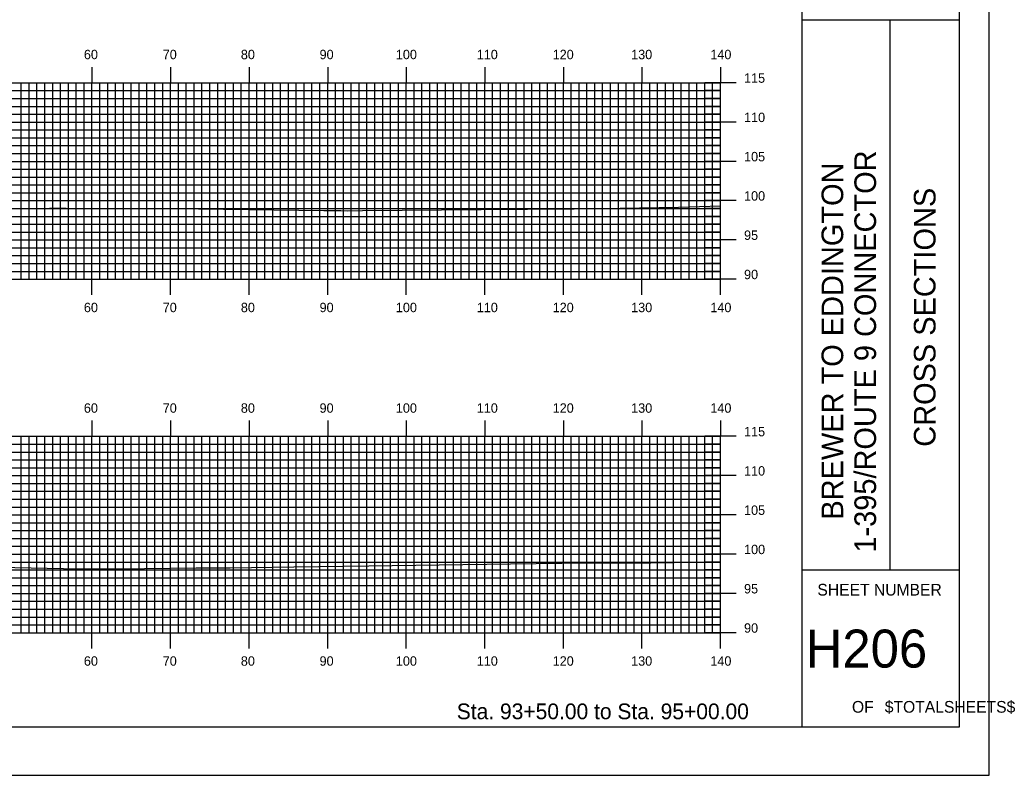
# Model space of a CAD drawing. Extents: x 1765333 to 1765676, y 442591 to 442811.
# Drawn here: x 1765549.2 to 1765675.9, y 442590.5 to 442686.7 of the extents above; entities that cross this region are included whole.
import ezdxf

# ---------------------------------------------------------------- set-up
doc = ezdxf.new("R2010")
doc.units = 0
for name, color, linetype in [('BORDER', 7, 'Continuous'), ('H_V ANNOTATION', 7, 'Continuous'), ('MAJOR', 7, 'Continuous'), ('MINOR', 7, 'Continuous'), ('PLOT BOUNDARY', 7, 'Continuous'), ('S_Roadway_Centerline', 7, 'Continuous')]:
    doc.layers.add(name, color=color, linetype=linetype)

msp = doc.modelspace()

# ---------------------------------------------------------------- linework, layer by layer
at = {"layer": 'BORDER'}
for p, q in [((1765648.77, 442596.67), (1765648.77, 442806.67)), ((1765648.77, 442686.67), (1765668.77, 442686.67)), ((1765659.95, 442616.67), (1765659.95, 442686.67)), ((1765648.77, 442616.67), (1765668.77, 442616.67))]:
    msp.add_line(p, q, dxfattribs=at)
msp.add_lwpolyline([(1765348.77, 442596.67), (1765668.77, 442596.67), (1765668.77, 442806.67), (1765348.77, 442806.67)], close=True, dxfattribs=at)
at = {"layer": 'MAJOR'}
for p, q in [((1765558.37, 442680.67), (1765558.37, 442678.67)), ((1765568.37, 442680.67), (1765568.37, 442678.67)), ((1765578.37, 442680.67), (1765578.37, 442678.67)), ((1765588.37, 442680.67), (1765588.37, 442678.67)), ((1765598.37, 442680.67), (1765598.37, 442678.67)), ((1765608.37, 442680.67), (1765608.37, 442678.67)), ((1765618.37, 442680.67), (1765618.37, 442678.67)), ((1765628.37, 442680.67), (1765628.37, 442678.67)), ((1765638.37, 442680.67), (1765638.37, 442678.67)), ((1765358.37, 442678.67), (1765638.37, 442678.67)), ((1765358.37, 442678.67), (1765638.37, 442678.67)), ((1765558.37, 442653.67), (1765558.37, 442678.67)), ((1765568.37, 442653.67), (1765568.37, 442678.67)), ((1765578.37, 442653.67), (1765578.37, 442678.67)), ((1765588.37, 442653.67), (1765588.37, 442678.67)), ((1765598.37, 442653.67), (1765598.37, 442678.67)), ((1765608.37, 442653.67), (1765608.37, 442678.67)), ((1765618.37, 442653.67), (1765618.37, 442678.67)), ((1765628.37, 442653.67), (1765628.37, 442678.67)), ((1765640.37, 442678.67), (1765636.37, 442678.67)), ((1765638.37, 442653.67), (1765638.37, 442678.67)), ((1765638.37, 442653.67), (1765638.37, 442678.67)), ((1765358.37, 442673.67), (1765638.37, 442673.67)), ((1765640.37, 442673.67), (1765636.37, 442673.67)), ((1765358.37, 442668.67), (1765638.37, 442668.67)), ((1765640.37, 442668.67), (1765636.37, 442668.67)), ((1765358.37, 442663.67), (1765638.37, 442663.67)), ((1765640.37, 442663.67), (1765636.37, 442663.67)), ((1765358.37, 442658.67), (1765638.37, 442658.67)), ((1765640.37, 442658.67), (1765636.37, 442658.67)), ((1765358.37, 442653.67), (1765638.37, 442653.67)), ((1765358.37, 442653.67), (1765638.37, 442653.67)), ((1765558.37, 442651.66), (1765558.37, 442653.67)), ((1765568.37, 442651.66), (1765568.37, 442653.67)), ((1765578.37, 442651.66), (1765578.37, 442653.67)), ((1765588.37, 442651.66), (1765588.37, 442653.67)), ((1765598.37, 442651.66), (1765598.37, 442653.67)), ((1765608.37, 442651.66), (1765608.37, 442653.67)), ((1765618.37, 442651.66), (1765618.37, 442653.67)), ((1765628.37, 442651.66), (1765628.37, 442653.67)), ((1765640.37, 442653.67), (1765636.37, 442653.67)), ((1765638.37, 442651.66), (1765638.37, 442653.67)), ((1765558.37, 442635.67), (1765558.37, 442633.67)), ((1765568.37, 442635.67), (1765568.37, 442633.67)), ((1765578.37, 442635.67), (1765578.37, 442633.67)), ((1765588.37, 442635.67), (1765588.37, 442633.67)), ((1765598.37, 442635.67), (1765598.37, 442633.67)), ((1765608.37, 442635.67), (1765608.37, 442633.67)), ((1765618.37, 442635.67), (1765618.37, 442633.67)), ((1765628.37, 442635.67), (1765628.37, 442633.67)), ((1765638.37, 442635.67), (1765638.37, 442633.67)), ((1765358.37, 442633.67), (1765638.37, 442633.67)), ((1765358.37, 442633.67), (1765638.37, 442633.67)), ((1765558.37, 442608.67), (1765558.37, 442633.67)), ((1765568.37, 442608.67), (1765568.37, 442633.67)), ((1765578.37, 442608.67), (1765578.37, 442633.67)), ((1765588.37, 442608.67), (1765588.37, 442633.67)), ((1765598.37, 442608.67), (1765598.37, 442633.67)), ((1765608.37, 442608.67), (1765608.37, 442633.67)), ((1765618.37, 442608.67), (1765618.37, 442633.67)), ((1765628.37, 442608.67), (1765628.37, 442633.67)), ((1765640.37, 442633.67), (1765636.37, 442633.67)), ((1765638.37, 442608.67), (1765638.37, 442633.67)), ((1765638.37, 442608.67), (1765638.37, 442633.67)), ((1765358.37, 442628.67), (1765638.37, 442628.67)), ((1765640.37, 442628.67), (1765636.37, 442628.67)), ((1765358.37, 442623.67), (1765638.37, 442623.67)), ((1765640.37, 442623.67), (1765636.37, 442623.67)), ((1765358.37, 442618.67), (1765638.37, 442618.67)), ((1765640.37, 442618.67), (1765636.37, 442618.67)), ((1765358.37, 442613.67), (1765638.37, 442613.67)), ((1765640.37, 442613.67), (1765636.37, 442613.67)), ((1765358.37, 442608.67), (1765638.37, 442608.67)), ((1765358.37, 442608.67), (1765638.37, 442608.67)), ((1765558.37, 442606.66), (1765558.37, 442608.67)), ((1765568.37, 442606.66), (1765568.37, 442608.67)), ((1765578.37, 442606.66), (1765578.37, 442608.67)), ((1765588.37, 442606.66), (1765588.37, 442608.67)), ((1765598.37, 442606.66), (1765598.37, 442608.67)), ((1765608.37, 442606.66), (1765608.37, 442608.67)), ((1765618.37, 442606.66), (1765618.37, 442608.67)), ((1765628.37, 442606.66), (1765628.37, 442608.67)), ((1765640.37, 442608.67), (1765636.37, 442608.67)), ((1765638.37, 442606.66), (1765638.37, 442608.67))]:
    msp.add_line(p, q, dxfattribs=at)
at = {"layer": 'MINOR'}
for p, q in [((1765549.37, 442653.67), (1765549.37, 442678.67)), ((1765550.37, 442653.67), (1765550.37, 442678.67)), ((1765551.37, 442653.67), (1765551.37, 442678.67)), ((1765552.37, 442653.67), (1765552.37, 442678.67)), ((1765553.37, 442653.67), (1765553.37, 442678.67)), ((1765554.37, 442653.67), (1765554.37, 442678.67)), ((1765555.37, 442653.67), (1765555.37, 442678.67)), ((1765556.37, 442653.67), (1765556.37, 442678.67)), ((1765557.37, 442653.67), (1765557.37, 442678.67)), ((1765559.37, 442653.67), (1765559.37, 442678.67)), ((1765560.37, 442653.67), (1765560.37, 442678.67)), ((1765561.37, 442653.67), (1765561.37, 442678.67)), ((1765562.37, 442653.67), (1765562.37, 442678.67)), ((1765563.37, 442653.67), (1765563.37, 442678.67)), ((1765564.37, 442653.67), (1765564.37, 442678.67)), ((1765565.37, 442653.67), (1765565.37, 442678.67)), ((1765566.37, 442653.67), (1765566.37, 442678.67)), ((1765567.37, 442653.67), (1765567.37, 442678.67)), ((1765569.37, 442653.67), (1765569.37, 442678.67)), ((1765570.37, 442653.67), (1765570.37, 442678.67)), ((1765571.37, 442653.67), (1765571.37, 442678.67)), ((1765572.37, 442653.67), (1765572.37, 442678.67)), ((1765573.37, 442653.67), (1765573.37, 442678.67)), ((1765574.37, 442653.67), (1765574.37, 442678.67)), ((1765575.37, 442653.67), (1765575.37, 442678.67)), ((1765576.37, 442653.67), (1765576.37, 442678.67)), ((1765577.37, 442653.67), (1765577.37, 442678.67)), ((1765579.37, 442653.67), (1765579.37, 442678.67)), ((1765580.37, 442653.67), (1765580.37, 442678.67)), ((1765581.37, 442653.67), (1765581.37, 442678.67)), ((1765582.37, 442653.67), (1765582.37, 442678.67)), ((1765583.37, 442653.67), (1765583.37, 442678.67)), ((1765584.37, 442653.67), (1765584.37, 442678.67)), ((1765585.37, 442653.67), (1765585.37, 442678.67)), ((1765586.37, 442653.67), (1765586.37, 442678.67)), ((1765587.37, 442653.67), (1765587.37, 442678.67)), ((1765589.37, 442653.67), (1765589.37, 442678.67)), ((1765590.37, 442653.67), (1765590.37, 442678.67)), ((1765591.37, 442653.67), (1765591.37, 442678.67)), ((1765592.37, 442653.67), (1765592.37, 442678.67)), ((1765593.37, 442653.67), (1765593.37, 442678.67)), ((1765594.37, 442653.67), (1765594.37, 442678.67)), ((1765595.37, 442653.67), (1765595.37, 442678.67)), ((1765596.37, 442653.67), (1765596.37, 442678.67)), ((1765597.37, 442653.67), (1765597.37, 442678.67)), ((1765599.37, 442653.67), (1765599.37, 442678.67)), ((1765600.37, 442653.67), (1765600.37, 442678.67)), ((1765601.37, 442653.67), (1765601.37, 442678.67)), ((1765602.37, 442653.67), (1765602.37, 442678.67)), ((1765603.37, 442653.67), (1765603.37, 442678.67)), ((1765604.37, 442653.67), (1765604.37, 442678.67)), ((1765605.37, 442653.67), (1765605.37, 442678.67)), ((1765606.37, 442653.67), (1765606.37, 442678.67)), ((1765607.37, 442653.67), (1765607.37, 442678.67)), ((1765609.37, 442653.67), (1765609.37, 442678.67)), ((1765610.37, 442653.67), (1765610.37, 442678.67)), ((1765611.37, 442653.67), (1765611.37, 442678.67)), ((1765612.37, 442653.67), (1765612.37, 442678.67)), ((1765613.37, 442653.67), (1765613.37, 442678.67)), ((1765614.37, 442653.67), (1765614.37, 442678.67)), ((1765615.37, 442653.67), (1765615.37, 442678.67)), ((1765616.37, 442653.67), (1765616.37, 442678.67)), ((1765617.37, 442653.67), (1765617.37, 442678.67)), ((1765619.37, 442653.67), (1765619.37, 442678.67)), ((1765620.37, 442653.67), (1765620.37, 442678.67)), ((1765621.37, 442653.67), (1765621.37, 442678.67)), ((1765622.37, 442653.67), (1765622.37, 442678.67)), ((1765623.37, 442653.67), (1765623.37, 442678.67)), ((1765624.37, 442653.67), (1765624.37, 442678.67)), ((1765625.37, 442653.67), (1765625.37, 442678.67)), ((1765626.37, 442653.67), (1765626.37, 442678.67)), ((1765627.37, 442653.67), (1765627.37, 442678.67)), ((1765629.37, 442653.67), (1765629.37, 442678.67)), ((1765630.37, 442653.67), (1765630.37, 442678.67)), ((1765631.37, 442653.67), (1765631.37, 442678.67)), ((1765632.37, 442653.67), (1765632.37, 442678.67)), ((1765633.37, 442653.67), (1765633.37, 442678.67)), ((1765634.37, 442653.67), (1765634.37, 442678.67)), ((1765635.37, 442653.67), (1765635.37, 442678.67)), ((1765636.37, 442653.67), (1765636.37, 442678.67)), ((1765637.37, 442653.67), (1765637.37, 442678.67)), ((1765358.37, 442677.67), (1765638.37, 442677.67)), ((1765638.37, 442677.67), (1765636.37, 442677.67)), ((1765358.37, 442676.67), (1765638.37, 442676.67)), ((1765638.37, 442676.67), (1765636.37, 442676.67)), ((1765358.37, 442675.67), (1765638.37, 442675.67)), ((1765638.37, 442675.67), (1765636.37, 442675.67)), ((1765358.37, 442674.67), (1765638.37, 442674.67)), ((1765638.37, 442674.67), (1765636.37, 442674.67)), ((1765358.37, 442672.67), (1765638.37, 442672.67)), ((1765638.37, 442672.67), (1765636.37, 442672.67)), ((1765358.37, 442671.67), (1765638.37, 442671.67)), ((1765638.37, 442671.67), (1765636.37, 442671.67)), ((1765358.37, 442670.67), (1765638.37, 442670.67)), ((1765638.37, 442670.67), (1765636.37, 442670.67)), ((1765358.37, 442669.67), (1765638.37, 442669.67)), ((1765638.37, 442669.67), (1765636.37, 442669.67)), ((1765358.37, 442667.67), (1765638.37, 442667.67)), ((1765638.37, 442667.67), (1765636.37, 442667.67)), ((1765358.37, 442666.67), (1765638.37, 442666.67)), ((1765638.37, 442666.67), (1765636.37, 442666.67)), ((1765358.37, 442665.67), (1765638.37, 442665.67)), ((1765358.37, 442664.67), (1765638.37, 442664.67)), ((1765638.37, 442665.67), (1765636.37, 442665.67)), ((1765638.37, 442664.67), (1765636.37, 442664.67)), ((1765358.37, 442662.67), (1765638.37, 442662.67)), ((1765638.37, 442662.67), (1765636.37, 442662.67)), ((1765358.37, 442661.67), (1765638.37, 442661.67)), ((1765638.37, 442661.67), (1765636.37, 442661.67)), ((1765358.37, 442660.67), (1765638.37, 442660.67)), ((1765358.37, 442659.67), (1765638.37, 442659.67)), ((1765638.37, 442660.67), (1765636.37, 442660.67)), ((1765638.37, 442659.67), (1765636.37, 442659.67)), ((1765358.37, 442657.67), (1765638.37, 442657.67)), ((1765638.37, 442657.67), (1765636.37, 442657.67)), ((1765358.37, 442656.67), (1765638.37, 442656.67)), ((1765638.37, 442656.67), (1765636.37, 442656.67)), ((1765358.37, 442655.67), (1765638.37, 442655.67)), ((1765358.37, 442654.67), (1765638.37, 442654.67)), ((1765638.37, 442655.67), (1765636.37, 442655.67)), ((1765638.37, 442654.67), (1765636.37, 442654.67)), ((1765549.37, 442608.67), (1765549.37, 442633.67)), ((1765550.37, 442608.67), (1765550.37, 442633.67)), ((1765551.37, 442608.67), (1765551.37, 442633.67)), ((1765552.37, 442608.67), (1765552.37, 442633.67)), ((1765553.37, 442608.67), (1765553.37, 442633.67)), ((1765554.37, 442608.67), (1765554.37, 442633.67)), ((1765555.37, 442608.67), (1765555.37, 442633.67)), ((1765556.37, 442608.67), (1765556.37, 442633.67)), ((1765557.37, 442608.67), (1765557.37, 442633.67)), ((1765559.37, 442608.67), (1765559.37, 442633.67)), ((1765560.37, 442608.67), (1765560.37, 442633.67)), ((1765561.37, 442608.67), (1765561.37, 442633.67)), ((1765562.37, 442608.67), (1765562.37, 442633.67)), ((1765563.37, 442608.67), (1765563.37, 442633.67)), ((1765564.37, 442608.67), (1765564.37, 442633.67)), ((1765565.37, 442608.67), (1765565.37, 442633.67)), ((1765566.37, 442608.67), (1765566.37, 442633.67)), ((1765567.37, 442608.67), (1765567.37, 442633.67)), ((1765569.37, 442608.67), (1765569.37, 442633.67)), ((1765570.37, 442608.67), (1765570.37, 442633.67)), ((1765571.37, 442608.67), (1765571.37, 442633.67)), ((1765572.37, 442608.67), (1765572.37, 442633.67)), ((1765573.37, 442608.67), (1765573.37, 442633.67)), ((1765574.37, 442608.67), (1765574.37, 442633.67)), ((1765575.37, 442608.67), (1765575.37, 442633.67)), ((1765576.37, 442608.67), (1765576.37, 442633.67)), ((1765577.37, 442608.67), (1765577.37, 442633.67)), ((1765579.37, 442608.67), (1765579.37, 442633.67)), ((1765580.37, 442608.67), (1765580.37, 442633.67)), ((1765581.37, 442608.67), (1765581.37, 442633.67)), ((1765582.37, 442608.67), (1765582.37, 442633.67)), ((1765583.37, 442608.67), (1765583.37, 442633.67)), ((1765584.37, 442608.67), (1765584.37, 442633.67)), ((1765585.37, 442608.67), (1765585.37, 442633.67)), ((1765586.37, 442608.67), (1765586.37, 442633.67)), ((1765587.37, 442608.67), (1765587.37, 442633.67)), ((1765589.37, 442608.67), (1765589.37, 442633.67)), ((1765590.37, 442608.67), (1765590.37, 442633.67)), ((1765591.37, 442608.67), (1765591.37, 442633.67)), ((1765592.37, 442608.67), (1765592.37, 442633.67)), ((1765593.37, 442608.67), (1765593.37, 442633.67)), ((1765594.37, 442608.67), (1765594.37, 442633.67)), ((1765595.37, 442608.67), (1765595.37, 442633.67)), ((1765596.37, 442608.67), (1765596.37, 442633.67)), ((1765597.37, 442608.67), (1765597.37, 442633.67)), ((1765599.37, 442608.67), (1765599.37, 442633.67)), ((1765600.37, 442608.67), (1765600.37, 442633.67)), ((1765601.37, 442608.67), (1765601.37, 442633.67)), ((1765602.37, 442608.67), (1765602.37, 442633.67)), ((1765603.37, 442608.67), (1765603.37, 442633.67)), ((1765604.37, 442608.67), (1765604.37, 442633.67)), ((1765605.37, 442608.67), (1765605.37, 442633.67)), ((1765606.37, 442608.67), (1765606.37, 442633.67)), ((1765607.37, 442608.67), (1765607.37, 442633.67)), ((1765609.37, 442608.67), (1765609.37, 442633.67)), ((1765610.37, 442608.67), (1765610.37, 442633.67)), ((1765611.37, 442608.67), (1765611.37, 442633.67)), ((1765612.37, 442608.67), (1765612.37, 442633.67)), ((1765613.37, 442608.67), (1765613.37, 442633.67)), ((1765614.37, 442608.67), (1765614.37, 442633.67)), ((1765615.37, 442608.67), (1765615.37, 442633.67)), ((1765616.37, 442608.67), (1765616.37, 442633.67)), ((1765617.37, 442608.67), (1765617.37, 442633.67)), ((1765619.37, 442608.67), (1765619.37, 442633.67)), ((1765620.37, 442608.67), (1765620.37, 442633.67)), ((1765621.37, 442608.67), (1765621.37, 442633.67)), ((1765622.37, 442608.67), (1765622.37, 442633.67)), ((1765623.37, 442608.67), (1765623.37, 442633.67)), ((1765624.37, 442608.67), (1765624.37, 442633.67)), ((1765625.37, 442608.67), (1765625.37, 442633.67)), ((1765626.37, 442608.67), (1765626.37, 442633.67)), ((1765627.37, 442608.67), (1765627.37, 442633.67)), ((1765629.37, 442608.67), (1765629.37, 442633.67)), ((1765630.37, 442608.67), (1765630.37, 442633.67)), ((1765631.37, 442608.67), (1765631.37, 442633.67)), ((1765632.37, 442608.67), (1765632.37, 442633.67)), ((1765633.37, 442608.67), (1765633.37, 442633.67)), ((1765634.37, 442608.67), (1765634.37, 442633.67)), ((1765635.37, 442608.67), (1765635.37, 442633.67)), ((1765636.37, 442608.67), (1765636.37, 442633.67)), ((1765637.37, 442608.67), (1765637.37, 442633.67)), ((1765358.37, 442632.67), (1765638.37, 442632.67)), ((1765638.37, 442632.67), (1765636.37, 442632.67)), ((1765358.37, 442631.67), (1765638.37, 442631.67)), ((1765358.37, 442630.67), (1765638.37, 442630.67)), ((1765638.37, 442631.67), (1765636.37, 442631.67)), ((1765638.37, 442630.67), (1765636.37, 442630.67)), ((1765358.37, 442629.67), (1765638.37, 442629.67)), ((1765638.37, 442629.67), (1765636.37, 442629.67)), ((1765358.37, 442627.67), (1765638.37, 442627.67)), ((1765358.37, 442626.67), (1765638.37, 442626.67)), ((1765638.37, 442627.67), (1765636.37, 442627.67)), ((1765638.37, 442626.67), (1765636.37, 442626.67)), ((1765358.37, 442625.67), (1765638.37, 442625.67)), ((1765638.37, 442625.67), (1765636.37, 442625.67)), ((1765358.37, 442624.67), (1765638.37, 442624.67)), ((1765638.37, 442624.67), (1765636.37, 442624.67)), ((1765358.37, 442622.67), (1765638.37, 442622.67)), ((1765358.37, 442621.67), (1765638.37, 442621.67)), ((1765638.37, 442622.67), (1765636.37, 442622.67)), ((1765638.37, 442621.67), (1765636.37, 442621.67)), ((1765358.37, 442620.67), (1765638.37, 442620.67)), ((1765638.37, 442620.67), (1765636.37, 442620.67)), ((1765358.37, 442619.67), (1765638.37, 442619.67)), ((1765638.37, 442619.67), (1765636.37, 442619.67)), ((1765358.37, 442617.67), (1765638.37, 442617.67)), ((1765358.37, 442616.67), (1765638.37, 442616.67)), ((1765638.37, 442617.67), (1765636.37, 442617.67)), ((1765638.37, 442616.67), (1765636.37, 442616.67)), ((1765358.37, 442615.67), (1765638.37, 442615.67)), ((1765638.37, 442615.67), (1765636.37, 442615.67)), ((1765358.37, 442614.67), (1765638.37, 442614.67)), ((1765638.37, 442614.67), (1765636.37, 442614.67)), ((1765358.37, 442612.67), (1765638.37, 442612.67)), ((1765358.37, 442611.67), (1765638.37, 442611.67)), ((1765638.37, 442612.67), (1765636.37, 442612.67)), ((1765638.37, 442611.67), (1765636.37, 442611.67)), ((1765358.37, 442610.67), (1765638.37, 442610.67)), ((1765638.37, 442610.67), (1765636.37, 442610.67)), ((1765358.37, 442609.67), (1765638.37, 442609.67)), ((1765638.37, 442609.67), (1765636.37, 442609.67))]:
    msp.add_line(p, q, dxfattribs=at)
at = {"layer": 'PLOT BOUNDARY'}
msp.add_lwpolyline([(1765332.58, 442590.55), (1765672.58, 442590.55), (1765672.58, 442810.55), (1765332.58, 442810.55)], close=True, dxfattribs=at)
at = {"layer": 'S_Roadway_Centerline'}
for points in [[(1765535.88, 442662.67), (1765552.97, 442662.71), (1765554.2, 442662.71), (1765555.08, 442662.7), (1765571.91, 442662.62), (1765587.87, 442662.43), (1765590.03, 442662.42), (1765590.88, 442662.39), (1765592.81, 442662.42), (1765607.91, 442662.52), (1765619.73, 442662.64), (1765625.58, 442662.7), (1765633.01, 442662.84), (1765638.37, 442662.99)], [(1765540.25, 442617.13), (1765554.75, 442616.85), (1765557.8, 442616.81), (1765561.75, 442616.81), (1765571.64, 442616.93), (1765575.95, 442616.94), (1765584.05, 442617.04), (1765593.62, 442617.2), (1765602.56, 442617.33), (1765611.63, 442617.42), (1765621.43, 442617.56), (1765629.51, 442617.58), (1765638.37, 442617.7)]]:
    msp.add_lwpolyline(points, dxfattribs=at)

# ---------------------------------------------------------------- texts
at = {"layer": 'BORDER'}
for s, p in [('1-395/ROUTE 9 CONNECTOR', (1765658.17, 442618.87)), ('BREWER TO EDDINGTON', (1765653.99, 442623.07)), ('CROSS SECTIONS', (1765665.74, 442632.34))]:
    msp.add_text(s, height=2.7557, rotation=90, dxfattribs=at).set_placement(p)
for s, height, p in [('SHEET NUMBER', 1.4905, (1765650.7, 442613.4)), ('H206', 4.839, (1765649.21, 442604.23)), ('$TOTALSHEETS$', 1.4905, (1765659.28, 442598.49)), ('OF', 1.491, (1765655.1, 442598.49))]:
    msp.add_text(s, height=height, dxfattribs=at).set_placement(p)
at = {"layer": 'H_V ANNOTATION'}
for s, height, p in [('60', 1.2, (1765557.34, 442681.67)), ('70', 1.2, (1765567.38, 442681.67)), ('80', 1.2, (1765577.32, 442681.67)), ('90', 1.2, (1765587.34, 442681.67)), ('100', 1.2, (1765597.05, 442681.67)), ('110', 1.2, (1765607.35, 442681.67)), ('120', 1.2, (1765617.01, 442681.67)), ('130', 1.2, (1765627, 442681.67)), ('140', 1.2, (1765637.08, 442681.67)), ('115', 1.2, (1765641.37, 442678.67)), ('110', 1.2, (1765641.37, 442673.67)), ('105', 1.2, (1765641.37, 442668.67)), ('100', 1.2, (1765641.37, 442663.67)), ('95', 1.2, (1765641.37, 442658.67)), ('90', 1.2, (1765641.37, 442653.67)), ('60', 1.2, (1765557.34, 442649.47)), ('70', 1.2, (1765567.38, 442649.47)), ('80', 1.2, (1765577.32, 442649.47)), ('90', 1.2, (1765587.34, 442649.47)), ('100', 1.2, (1765597.05, 442649.47)), ('110', 1.2, (1765607.35, 442649.47)), ('120', 1.2, (1765617.01, 442649.47)), ('130', 1.2, (1765627, 442649.47)), ('140', 1.2, (1765637.08, 442649.47)), ('60', 1.2, (1765557.34, 442636.67)), ('70', 1.2, (1765567.38, 442636.67)), ('80', 1.2, (1765577.32, 442636.67)), ('90', 1.2, (1765587.34, 442636.67)), ('100', 1.2, (1765597.05, 442636.67)), ('110', 1.2, (1765607.35, 442636.67)), ('120', 1.2, (1765617.01, 442636.67)), ('130', 1.2, (1765627, 442636.67)), ('140', 1.2, (1765637.08, 442636.67)), ('115', 1.2, (1765641.37, 442633.67)), ('110', 1.2, (1765641.37, 442628.67)), ('105', 1.2, (1765641.37, 442623.67)), ('100', 1.2, (1765641.37, 442618.67)), ('95', 1.2, (1765641.37, 442613.67)), ('90', 1.2, (1765641.37, 442608.67)), ('60', 1.2, (1765557.34, 442604.47)), ('70', 1.2, (1765567.38, 442604.47)), ('80', 1.2, (1765577.32, 442604.47)), ('90', 1.2, (1765587.34, 442604.47)), ('100', 1.2, (1765597.05, 442604.47)), ('110', 1.2, (1765607.35, 442604.47)), ('120', 1.2, (1765617.01, 442604.47)), ('130', 1.2, (1765627, 442604.47)), ('140', 1.2, (1765637.08, 442604.47)), ('Sta. 93+50.00 to Sta. 95+00.00', 2.0004, (1765604.8, 442597.66))]:
    msp.add_text(s, height=height, dxfattribs=at).set_placement(p)

doc.saveas('drawing.dxf')
